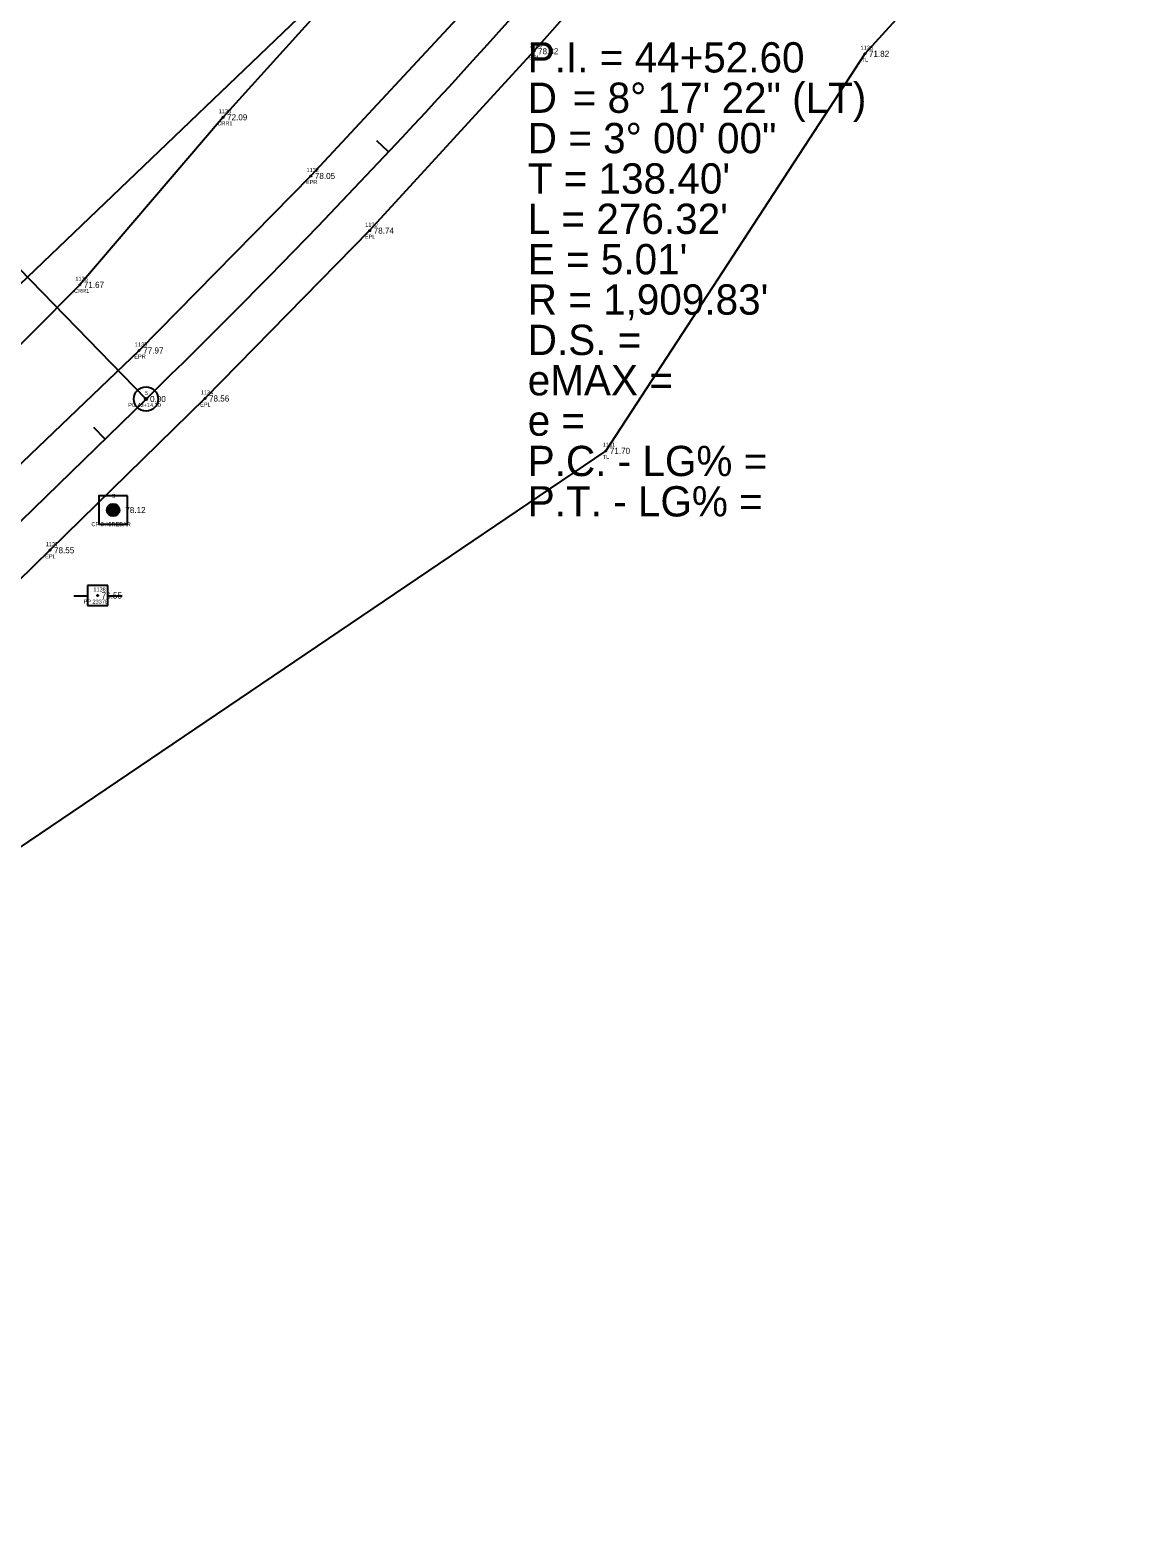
# Model space of a CAD drawing. Extents: x 2505249 to 2506333, y 912937 to 914171.
# Drawn here: x 2505580.7 to 2505855.2, y 913005.9 to 913379.5 of the extents above; entities that cross this region are included whole.
import ezdxf

# ---------------------------------------------------------------- set-up
doc = ezdxf.new("R2010")
doc.units = 0
for name, color, linetype in [('RD_EX_H2O', 7, 'Continuous'), ('RD_EX_H2O_txCode', 7, 'Continuous'), ('RD_EX_Road', 7, 'Continuous'), ('RD_EX_Road_txCode', 7, 'Continuous'), ('RD_EX_TX_H2O_ELEV', 7, 'Continuous'), ('RD_EX_TX_Road_ELEV', 7, 'Continuous'), ('RD_EX_TX_VEG_ELEV', 7, 'Continuous'), ('RD_EX_UT', 7, 'Continuous'), ('RD_EX_UT_txCode', 7, 'Continuous'), ('RD_EX_VEG', 7, 'Continuous'), ('RD_EX_VEG_txCode', 7, 'Continuous'), ('RD_HC_Cl', 7, 'Continuous'), ('RD_HC_Data', 7, 'Continuous'), ('RD_HC_Data_Tic', 7, 'Continuous'), ('RD_HC_Survey', 7, 'Continuous'), ('RD_HC_Survey_ELEV', 7, 'Continuous'), ('RD_HC_Survey_txCode', 7, 'Continuous'), ('RD_HC_txCode', 7, 'Continuous'), ('RD_SMD_Locator', 7, 'Continuous')]:
    doc.layers.add(name, color=color, linetype=linetype)

msp = doc.modelspace()

# ---------------------------------------------------------------- linework, layer by layer
at = {"layer": 'RD_EX_H2O'}
msp.add_lwpolyline([(2505789.47, 913464.31), (2505758.18, 913486.1), (2505736.66, 913480.49), (2505719.32, 913463.86), (2505699.9, 913439.21), (2505669.03, 913402.75), (2505628.5, 913357.9), (2505593, 913316.39), (2505556.58, 913279.8), (2505487.72, 913211.38), (2505413.81, 913149.81), (2505341.31, 913072.1)], dxfattribs=at)
at = {"layer": 'RD_EX_Road'}
for points in [[(2505758.23, 913470.96), (2505754.11, 913462.85), (2505725.4, 913427.85), (2505690.77, 913387.11), (2505650.25, 913343.36), (2505607.72, 913300.12), (2505570.97, 913264.99), (2505501.53, 913196.72), (2505431.76, 913128.83), (2505356.25, 913055.37)], [(2505777.56, 913455.88), (2505770.31, 913449.85), (2505741, 913414.45), (2505705.55, 913374.27), (2505664.83, 913329.82), (2505624.02, 913288.23), (2505585.62, 913250.63), (2505516.95, 913183.5), (2505444.27, 913113.56), (2505370.6, 913041.78)]]:
    msp.add_lwpolyline(points, dxfattribs=at)
at = {"layer": 'RD_EX_UT'}
for p, q in [((2505599.92, 913241.92), (2505594.92, 913241.92)), ((2505594.92, 913241.92), (2505594.92, 913236.92)), ((2505599.92, 913236.92), (2505599.92, 913241.92)), ((2505591.49, 913239.36), (2505594.96, 913239.36)), ((2505599.85, 913239.36), (2505603.49, 913239.36)), ((2505594.92, 913236.92), (2505599.92, 913236.92))]:
    msp.add_line(p, q, dxfattribs=at)
at = {"layer": 'RD_EX_VEG'}
for points in [[(2506002.64, 913815.25), (2505883.7, 913669.64), (2505827.83, 913593.29), (2505814.43, 913589.15), (2505792.49, 913560.55), (2505725.64, 913468.24), (2505664.37, 913399.09), (2505478.33, 913221), (2505411.99, 913152.19), (2505339.13, 913074.53)], [(2505850.96, 913443.27), (2505787.55, 913373.63), (2505723.35, 913275.26), (2505541.65, 913152.37), (2505470.96, 913075.44), (2505402.9, 913005.93)]]:
    msp.add_lwpolyline(points, dxfattribs=at)
at = {"layer": 'RD_HC_Cl'}
msp.add_line((2505363.33, 913048.43), (2505609.42, 913288.1), dxfattribs=at)
msp.add_arc((2504276.95, 914656.3), 1909.83, 314.24205, 322.53164, dxfattribs=at)
at = {"layer": 'RD_HC_Data'}
msp.add_line((2505609.42, 913288.1), (2505528.01, 913371.7), dxfattribs=at)
for radius in [3, 0.282]:
    msp.add_circle((2505609.42, 913288.1), radius, dxfattribs=at)
at = {"layer": 'RD_HC_Data_Tic'}
for p, q in [((2505669.53, 913349.33), (2505666.61, 913352.06)), ((2505599.25, 913278.2), (2505596.46, 913281.06))]:
    msp.add_line(p, q, dxfattribs=at)
at = {"layer": 'RD_HC_Survey'}
for p, q in [((2505599.77, 913260.23), (2505599.77, 913260.95)), ((2505599.82, 913260.06), (2505599.82, 913261.12)), ((2505599.87, 913259.94), (2505599.87, 913261.24)), ((2505599.92, 913259.84), (2505599.92, 913261.34)), ((2505599.97, 913259.76), (2505599.97, 913261.43)), ((2505600.02, 913259.68), (2505600.02, 913261.5)), ((2505600.07, 913259.62), (2505600.07, 913261.57)), ((2505600.12, 913259.56), (2505600.12, 913261.62)), ((2505600.17, 913259.51), (2505600.17, 913261.68)), ((2505600.22, 913259.46), (2505600.22, 913261.73)), ((2505600.27, 913259.41), (2505600.27, 913261.77)), ((2505600.32, 913259.37), (2505600.32, 913261.81)), ((2505600.37, 913259.33), (2505600.37, 913261.85)), ((2505600.42, 913259.3), (2505600.42, 913261.89)), ((2505600.47, 913259.27), (2505600.47, 913261.92)), ((2505600.52, 913259.24), (2505600.52, 913261.95)), ((2505600.57, 913259.21), (2505600.57, 913261.97)), ((2505600.62, 913259.18), (2505600.62, 913262)), ((2505600.67, 913259.16), (2505600.67, 913262.02)), ((2505600.72, 913259.14), (2505600.72, 913262.04)), ((2505600.77, 913259.12), (2505600.77, 913262.06)), ((2505600.82, 913259.11), (2505600.82, 913262.08)), ((2505600.87, 913259.09), (2505600.87, 913262.09)), ((2505600.92, 913259.08), (2505600.92, 913262.1)), ((2505600.97, 913259.07), (2505600.97, 913262.11)), ((2505601.02, 913259.06), (2505601.02, 913262.12)), ((2505601.07, 913259.05), (2505601.07, 913262.13)), ((2505601.12, 913259.05), (2505601.12, 913262.14)), ((2505601.17, 913259.04), (2505601.17, 913262.14)), ((2505601.22, 913259.04), (2505601.22, 913262.14)), ((2505601.27, 913259.04), (2505601.27, 913262.15)), ((2505601.32, 913259.04), (2505601.32, 913262.15)), ((2505601.37, 913259.04), (2505601.37, 913262.14)), ((2505601.42, 913259.04), (2505601.42, 913262.14)), ((2505601.47, 913259.05), (2505601.47, 913262.13)), ((2505601.52, 913259.06), (2505601.52, 913262.13)), ((2505601.57, 913259.06), (2505601.57, 913262.12)), ((2505601.62, 913259.07), (2505601.62, 913262.11)), ((2505601.67, 913259.09), (2505601.67, 913262.1)), ((2505601.72, 913259.1), (2505601.72, 913262.08)), ((2505601.77, 913259.12), (2505601.77, 913262.07)), ((2505601.82, 913259.13), (2505601.82, 913262.05)), ((2505601.87, 913259.15), (2505601.87, 913262.03)), ((2505601.92, 913259.17), (2505601.92, 913262.01)), ((2505601.97, 913259.2), (2505601.97, 913261.99)), ((2505602.02, 913259.22), (2505602.02, 913261.96)), ((2505602.07, 913259.25), (2505602.07, 913261.93)), ((2505602.12, 913259.28), (2505602.12, 913261.9)), ((2505602.17, 913259.32), (2505602.17, 913261.87)), ((2505602.22, 913259.35), (2505602.22, 913261.83)), ((2505602.27, 913259.39), (2505602.27, 913261.79)), ((2505602.32, 913259.43), (2505602.32, 913261.75)), ((2505602.37, 913259.48), (2505602.37, 913261.7)), ((2505602.42, 913259.53), (2505602.42, 913261.65)), ((2505602.47, 913259.59), (2505602.47, 913261.59)), ((2505602.52, 913259.65), (2505602.52, 913261.53)), ((2505602.57, 913259.72), (2505602.57, 913261.46)), ((2505602.62, 913259.8), (2505602.62, 913261.38)), ((2505602.67, 913259.89), (2505602.67, 913261.29)), ((2505602.72, 913260), (2505602.72, 913261.18)), ((2505602.77, 913260.14), (2505602.77, 913261.04)), ((2505602.82, 913260.37), (2505602.82, 913260.82))]:
    msp.add_line(p, q, dxfattribs=at)
msp.add_lwpolyline([(2505604.82, 913264.13), (2505597.75, 913264.13), (2505597.75, 913257.06), (2505604.82, 913257.06)], close=True, dxfattribs=at)
msp.add_circle((2505601.29, 913260.59), 1.55, dxfattribs=at)
at = {"layer": 'RD_SMD_Locator'}
for centre in [(2505705.55, 913374.27), (2505787.55, 913373.63), (2505628.5, 913357.9), (2505650.25, 913343.36), (2505664.83, 913329.82), (2505593, 913316.39), (2505607.72, 913300.12), (2505609.42, 913288.1), (2505624.02, 913288.23), (2505723.35, 913275.26), (2505601.29, 913260.59), (2505585.62, 913250.63), (2505597.43, 913239.41)]:
    msp.add_circle(centre, 0.15, dxfattribs=at)

# ---------------------------------------------------------------- texts
at = {"layer": 'RD_EX_H2O_txCode'}
for s, p in [('CRR1', (2505627.09, 913355.9)), ('1133', (2505627.44, 913358.9)), ('1136', (2505591.91, 913317.39)), ('CRR1', (2505591.58, 913314.39))]:
    msp.add_text(s, height=1, dxfattribs=at).set_placement(p)
at = {"layer": 'RD_EX_Road_txCode'}
for s, p in [('1126', (2505704.46, 913375.27)), ('EPL', (2505704.34, 913372.27)), ('EPR', (2505649.02, 913341.36)), ('1132', (2505649.19, 913344.36)), ('1130', (2505663.73, 913330.82)), ('EPL', (2505663.63, 913327.82)), ('1135', (2505606.66, 913301.12)), ('EPR', (2505606.49, 913298.12)), ('1134', (2505622.96, 913289.23)), ('EPL', (2505622.82, 913286.23)), ('1137', (2505584.56, 913251.63)), ('EPL', (2505584.42, 913248.63))]:
    msp.add_text(s, height=1, dxfattribs=at).set_placement(p)
at = {"layer": 'RD_EX_TX_H2O_ELEV'}
for s, p in [('72.09', (2505629.5, 913357.15)), ('71.67', (2505594, 913315.64))]:
    msp.add_text(s, height=1.5, dxfattribs=at).set_placement(p)
at = {"layer": 'RD_EX_TX_Road_ELEV'}
for s, p in [('78.82', (2505706.55, 913373.52)), ('78.05', (2505651.25, 913342.61)), ('78.74', (2505665.83, 913329.07)), ('77.97', (2505608.72, 913299.37)), ('78.56', (2505625.02, 913287.48)), ('78.55', (2505586.62, 913249.88))]:
    msp.add_text(s, height=1.5, dxfattribs=at).set_placement(p)
at = {"layer": 'RD_EX_TX_VEG_ELEV'}
for s, p in [('71.82', (2505788.55, 913372.88)), ('71.70', (2505724.35, 913274.51))]:
    msp.add_text(s, height=1.5, dxfattribs=at).set_placement(p)
at = {"layer": 'RD_EX_UT_txCode'}
for s, p in [('1138', (2505596.37, 913240.41)), ('PP 23378', (2505593.93, 913237.41))]:
    msp.add_text(s, height=1, dxfattribs=at).set_placement(p)
at = {"layer": 'RD_EX_VEG_txCode'}
for s, p in [('1123', (2505786.48, 913374.63)), ('TL', (2505786.77, 913371.63)), ('1131', (2505722.57, 913276.26)), ('TL', (2505722.58, 913273.26))]:
    msp.add_text(s, height=1, dxfattribs=at).set_placement(p)
at = {"layer": 'RD_HC_Data'}
for s, p in [('P.I. = 44+52.60', (2505704, 913369)), ('D', (2505704, 913359)), ('    = 8%%d 17\' 22" (LT)', (2505704, 913359)), ('D = 3%%d 00\' 00"', (2505704, 913349)), ("T = 138.40'", (2505704, 913339)), ("L = 276.32'", (2505704, 913329)), ("E = 5.01'", (2505704, 913319)), ("R = 1,909.83'", (2505704, 913309)), ('D.S. = ', (2505704, 913299)), ('eMAX = ', (2505704, 913289)), ('e = ', (2505704, 913279)), ('P.C. - LG% = ', (2505704, 913269)), ('P.T. - LG% = ', (2505704, 913259))]:
    msp.add_text(s, height=7.5, dxfattribs=at).set_placement(p)
at = {"layer": 'RD_HC_Survey_ELEV'}
for s, p in [('0.00', (2505610.42, 913287.35)), ('78.12', (2505604.29, 913259.84)), ('76.55', (2505598.43, 913238.66))]:
    msp.add_text(s, height=1.5, dxfattribs=at).set_placement(p)
at = {"layer": 'RD_HC_Survey_txCode'}
for s, p in [('3', (2505601, 913263.59)), ('CP 3 #5REBAR', (2505595.88, 913256.59))]:
    msp.add_text(s, height=1, dxfattribs=at).set_placement(p)
at = {"layer": 'RD_HC_txCode'}
for s, p in [('5', (2505609.14, 913289.1)), ('PC 43+14.20', (2505604.99, 913286.1))]:
    msp.add_text(s, height=1, dxfattribs=at).set_placement(p)

doc.saveas('drawing.dxf')
